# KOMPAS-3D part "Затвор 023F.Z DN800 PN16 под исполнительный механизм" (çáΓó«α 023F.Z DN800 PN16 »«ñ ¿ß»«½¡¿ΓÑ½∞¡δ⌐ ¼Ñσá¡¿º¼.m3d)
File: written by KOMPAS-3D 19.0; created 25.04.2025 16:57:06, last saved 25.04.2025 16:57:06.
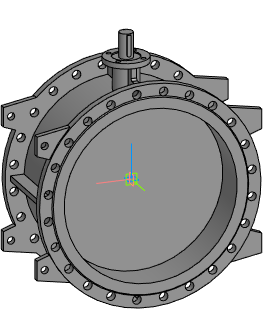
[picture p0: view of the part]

Document properties: Автор: Евгений; Полное имя файла: E:\Dendor Работа Сачек\3D для проекитирвщиков\1.7 Тип 023F.Z Затвор дисковый поворотный фланцевый с двумя эксцентриками\stp_Тип 023F.Z. Затвор под исполн. механизм\Затвор 023F.Z DN800 PN16 под исполнительный механизм.m3d

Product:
- Part/product: Затвор 023F.Z DN800 PN16 под исполнительный механизм

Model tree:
1. Операция без истории:1  (labels: Затвор 023F.Z DN800 PN16 под исполнительный механизм)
